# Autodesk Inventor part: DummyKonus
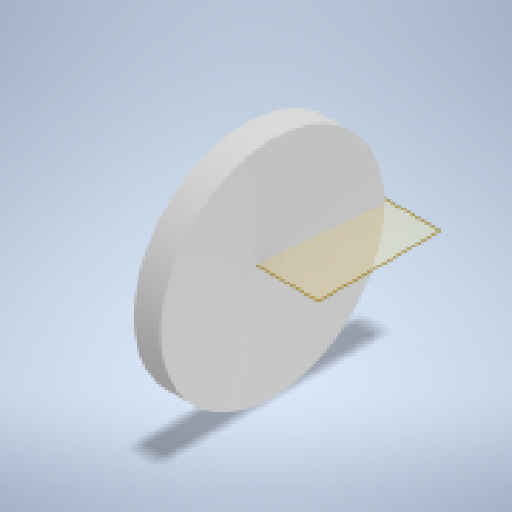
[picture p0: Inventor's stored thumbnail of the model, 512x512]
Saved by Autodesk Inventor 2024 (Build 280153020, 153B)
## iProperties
Created: 2024-06
Part Number: DummyKonus
Material: Generisch
Document SubType Name: Modeling
Designer: donndorf
Density: 1 g/cm^3
Appearance: Vorgabe
Author: donndorf
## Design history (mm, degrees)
workplane "Arbeitsebene2"
sketch "Skizze2"
  geometry: L1 (-129.807, 436.929)-(-183.369, -98.689) reference; L2 (-173.5, 0)-(-223.5, 0); L3 (-223.5, 0)-(-223.5, 350); L4 (-223.5, 350)-(-138.5, 350); L5 (-314.9, 0)-(324.9, 0) reference; 1 further point
  constraints: 8 end point, 3 point on line, 2 perpendicular, 1 horizontal, 3 other
  dimensions: "d0" = 350 distance of L2.end L3.end; "d1" = 50 distance of L2.start L2.end
revolve "Umdrehung1" sketch "Skizze2" stored, may be unused: angle "d2" = 90 deg
node "Volumenkörper1"
